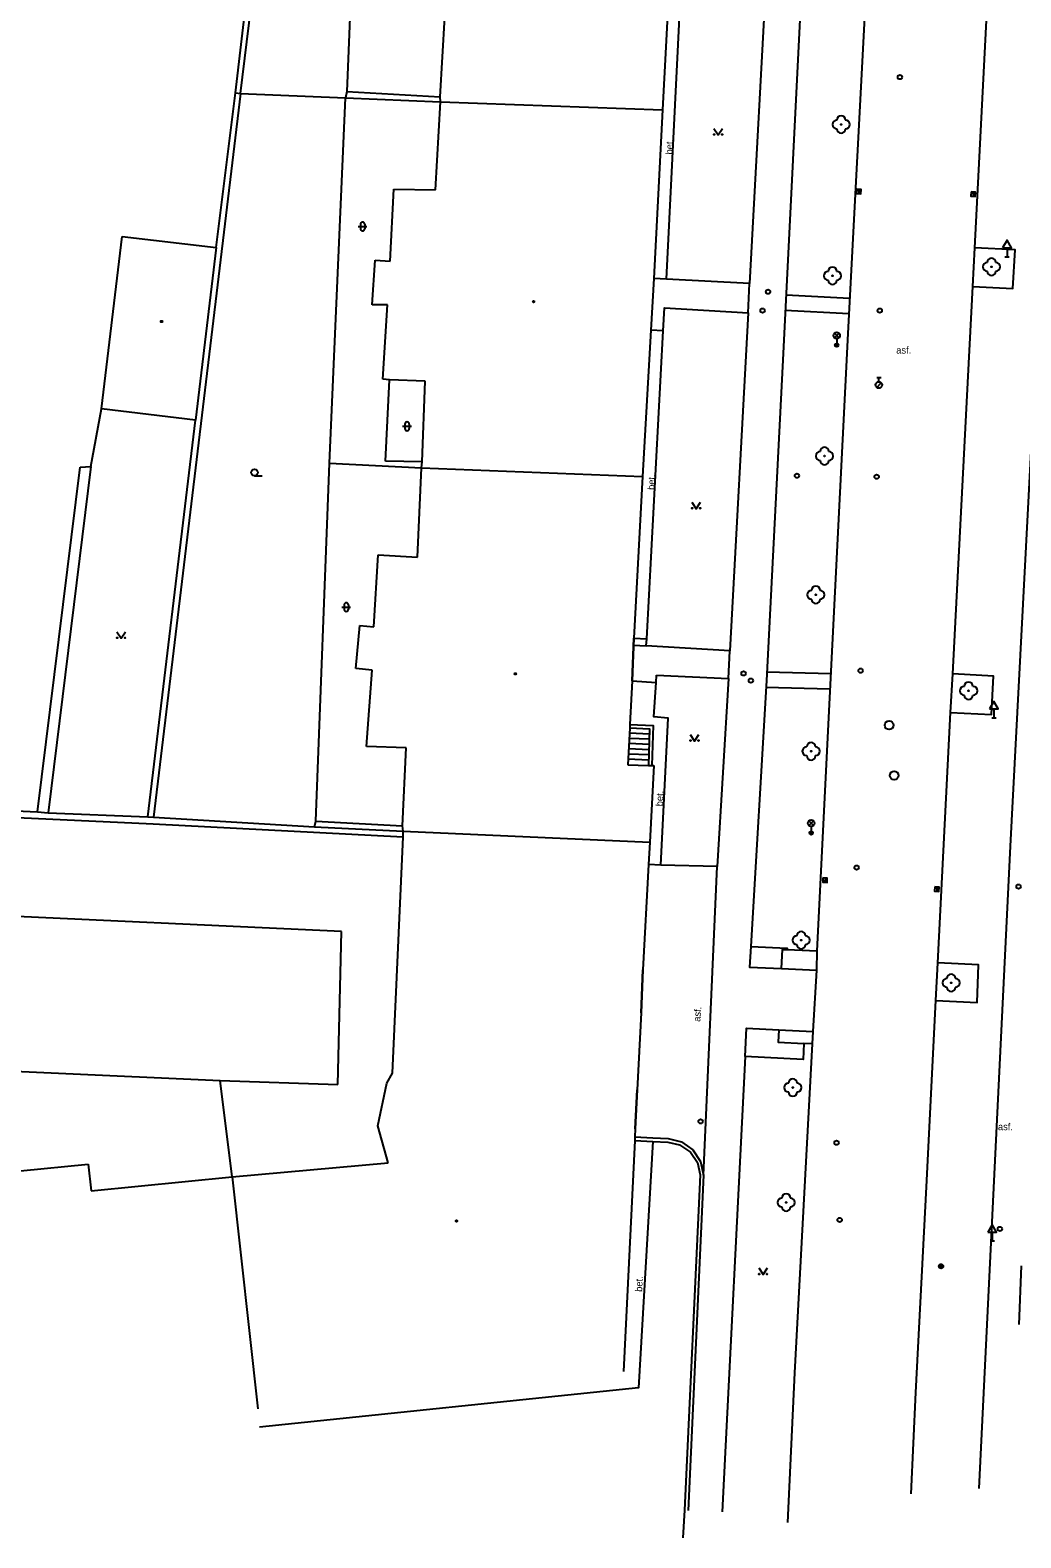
# Model space of a CAD drawing. Extents: x -599770 to -598493, y -1162076 to -1159209.
# Drawn here: x -599116.6 to -599059.8, y -1159858.3 to -1159771.9 of the extents above; entities that cross this region are included whole.
import ezdxf

# ---------------------------------------------------------------- set-up
doc = ezdxf.new("R2010")
doc.units = 0
doc.layers.add('Podklad', color=7, linetype='Continuous')

msp = doc.modelspace()

# ---------------------------------------------------------------- linework, layer by layer
at = {"layer": 'Podklad'}
for p, q in [((-599069.114, -1159781.055), (-599069.126, -1159781.305)), ((-599062.563, -1159781.215), (-599062.577, -1159781.465)), ((-599097.813, -1159783.188), (-599097.313, -1159783.188)), ((-599097.688, -1159783.063), (-599097.688, -1159783.313)), ((-599097.438, -1159783.063), (-599097.438, -1159783.313)), ((-599060.63, -1159784.411), (-599060.63, -1159784.92)), ((-599060.755, -1159784.92), (-599060.505, -1159784.92)), ((-599070.523, -1159789.56), (-599070.258, -1159789.295)), ((-599070.523, -1159789.295), (-599070.258, -1159789.56)), ((-599070.39, -1159789.615), (-599070.39, -1159789.99)), ((-599068.099, -1159792.406), (-599067.834, -1159792.141)), ((-599068.095, -1159791.832), (-599067.845, -1159791.832)), ((-599067.97, -1159792.082), (-599067.97, -1159791.832)), ((-599095.263, -1159794.638), (-599094.763, -1159794.638)), ((-599095.138, -1159794.513), (-599095.138, -1159794.763)), ((-599094.888, -1159794.513), (-599094.888, -1159794.763)), ((-599103.75, -1159797.477), (-599103.312, -1159797.477)), ((-599098.743, -1159804.998), (-599098.243, -1159804.998)), ((-599098.618, -1159804.873), (-599098.618, -1159805.123)), ((-599098.368, -1159804.873), (-599098.368, -1159805.123)), ((-599061.505, -1159811.34), (-599061.255, -1159811.34)), ((-599061.38, -1159810.831), (-599061.38, -1159811.34)), ((-599071.983, -1159817.51), (-599071.718, -1159817.245)), ((-599071.983, -1159817.245), (-599071.718, -1159817.51)), ((-599071.85, -1159817.565), (-599071.85, -1159817.94)), ((-599071.053, -1159820.515), (-599071.067, -1159820.765)), ((-599064.647, -1159821.035), (-599064.653, -1159821.285)), ((-599061.48, -1159840.811), (-599061.48, -1159841.32)), ((-599061.605, -1159841.32), (-599061.355, -1159841.32))]:
    msp.add_line(p, q, dxfattribs=at)
for points in [[(-599064.88, -1159693.54), (-599068.63, -1159693.23), (-599068.733, -1159695.648), (-599069.063, -1159703.385), (-599069.128, -1159704.902), (-599069.27, -1159708.23), (-599070.26, -1159727.69), (-599071.34, -1159749.23), (-599072.37, -1159768.64), (-599073.44, -1159790.08), (-599074.42, -1159809.21), (-599075.32, -1159824.45)], [(-599064.88, -1159693.54), (-599064.99, -1159695.953), (-599065.336, -1159703.585), (-599065.404, -1159705.083), (-599065.6, -1159709.4), (-599066.57, -1159727.92), (-599067.66, -1159748.75), (-599068.68, -1159768.99), (-599069.76, -1159789.32), (-599070.8, -1159810.19), (-599071.53, -1159824.7)], [(-599054.74, -1159709.09), (-599055.16, -1159717.05), (-599056.53, -1159743.1), (-599058.18, -1159775.24), (-599060.45, -1159818.7), (-599062.24, -1159855.51)], [(-599062.47, -1159784.41), (-599062.25, -1159779.95), (-599061.63, -1159768.01), (-599060.72, -1159751.04)], [(-599104.84, -1159775.52), (-599102.37, -1159754.5)], [(-599104.55, -1159775.56), (-599101.98, -1159754.51)], [(-599097.63, -1159754.74), (-599098.46, -1159775.46)], [(-599079.3, -1159769.29), (-599079.18, -1159766.89), (-599074.34, -1159767.07), (-599075.38, -1159786.45), (-599080.15, -1159786.21)], [(-599080, -1159769.26), (-599080.37, -1159776.51)], [(-599080.15, -1159786.21), (-599079.3, -1159769.29)], [(-599093.11, -1159775.75), (-599092.84, -1159771.18)], [(-599104.55, -1159775.56), (-599109.55, -1159817.03)], [(-599105.95, -1159784.4), (-599104.84, -1159775.52)], [(-599104.84, -1159775.52), (-599104.55, -1159775.56)], [(-599104.55, -1159775.56), (-599098.54, -1159775.82)], [(-599099.45, -1159796.75), (-599098.54, -1159775.82)], [(-599098.46, -1159775.46), (-599098.54, -1159775.82)], [(-599098.54, -1159775.82), (-599093.09, -1159776.05)], [(-599098.46, -1159775.46), (-599093.11, -1159775.75)], [(-599093.39, -1159781.08), (-599093.09, -1159776.05)], [(-599093.09, -1159776.05), (-599093.11, -1159775.75)], [(-599093.09, -1159776.05), (-599080.37, -1159776.51)], [(-599080.37, -1159776.51), (-599080.87, -1159786.17)], [(-599077.43, -1159777.565), (-599077.18, -1159777.94), (-599076.93, -1159777.565)], [(-599095.98, -1159785.18), (-599095.76, -1159781.05)], [(-599095.76, -1159781.05), (-599093.39, -1159781.08)], [(-599112.53, -1159793.63), (-599111.34, -1159783.76)], [(-599111.34, -1159783.76), (-599105.95, -1159784.4)], [(-599105.95, -1159784.4), (-599107.14, -1159794.28)], [(-599062.59, -1159786.63), (-599062.47, -1159784.41)], [(-599062.59, -1159786.63), (-599060.29, -1159786.75), (-599060.16, -1159784.53), (-599062.47, -1159784.41)], [(-599097.02, -1159787.68), (-599096.84, -1159785.11)], [(-599096.84, -1159785.11), (-599095.98, -1159785.18)], [(-599080.87, -1159786.17), (-599081.04, -1159789.13)], [(-599080.15, -1159786.21), (-599080.87, -1159786.17)], [(-599075.47, -1159788.13), (-599075.38, -1159786.45)], [(-599073.292, -1159787.112), (-599069.653, -1159787.299)], [(-599063.74, -1159808.83), (-599062.86, -1159791.77), (-599062.59, -1159786.63)], [(-599096.14, -1159787.68), (-599097.02, -1159787.68)], [(-599096.39, -1159791.93), (-599096.14, -1159787.68)], [(-599080.33, -1159789.17), (-599080.26, -1159787.84), (-599075.47, -1159788.13), (-599076.51, -1159807.51), (-599081.3, -1159807.21)], [(-599069.7, -1159788.198), (-599073.337, -1159788.011)], [(-599081.04, -1159789.13), (-599081.52, -1159797.52)], [(-599081.28, -1159806.82), (-599080.33, -1159789.17)], [(-599080.33, -1159789.17), (-599081.04, -1159789.13)], [(-599096.01, -1159791.98), (-599096.39, -1159791.93)], [(-599096.25, -1159796.64), (-599096.01, -1159791.98)], [(-599093.98, -1159792.06), (-599096.01, -1159791.98)], [(-599094.14, -1159796.68), (-599093.98, -1159792.06)], [(-599113.13, -1159796.95), (-599112.53, -1159793.63)], [(-599107.14, -1159794.28), (-599112.53, -1159793.63)], [(-599109.87, -1159817.02), (-599107.14, -1159794.28)], [(-599100.24, -1159817.26), (-599099.45, -1159796.75)], [(-599099.45, -1159796.75), (-599094.19, -1159797.01)], [(-599094.14, -1159796.68), (-599096.25, -1159796.64)], [(-599094.19, -1159797.01), (-599094.14, -1159796.68)], [(-599116.19, -1159816.73), (-599113.74, -1159796.98)], [(-599113.13, -1159796.95), (-599115.57, -1159816.78)], [(-599113.74, -1159796.98), (-599113.13, -1159796.95)], [(-599094.41, -1159802.13), (-599094.19, -1159797.01)], [(-599094.19, -1159797.01), (-599081.52, -1159797.52)], [(-599081.52, -1159797.52), (-599082.01, -1159806.77)], [(-599078.69, -1159798.985), (-599078.44, -1159799.36), (-599078.19, -1159798.985)], [(-599096.92, -1159806.13), (-599096.66, -1159802.01)], [(-599096.66, -1159802.01), (-599094.41, -1159802.13)], [(-599097.94, -1159808.51), (-599097.72, -1159806.05)], [(-599097.72, -1159806.05), (-599096.92, -1159806.13)], [(-599111.65, -1159806.405), (-599111.4, -1159806.78), (-599111.15, -1159806.405)], [(-599082.12, -1159809.22), (-599082.01, -1159806.77)], [(-599082.01, -1159806.77), (-599082.12, -1159809.22)], [(-599082.028, -1159807.18), (-599081.3, -1159807.21)], [(-599082.01, -1159806.77), (-599081.28, -1159806.82)], [(-599081.3, -1159807.21), (-599081.28, -1159806.82)], [(-599076.6, -1159809.08), (-599076.51, -1159807.51)], [(-599097.02, -1159808.62), (-599097.94, -1159808.51)], [(-599097.34, -1159812.99), (-599097.02, -1159808.62)], [(-599080.74, -1159809.32), (-599080.71, -1159808.9)], [(-599080.71, -1159808.9), (-599076.6, -1159809.08), (-599077.24, -1159819.87), (-599080.47, -1159819.78)], [(-599074.394, -1159808.701), (-599070.731, -1159808.799)], [(-599063.86, -1159811.04), (-599063.74, -1159808.83)], [(-599063.86, -1159811.04), (-599061.52, -1159811.15), (-599061.41, -1159808.95), (-599063.74, -1159808.83)], [(-599082.12, -1159809.22), (-599082.24, -1159811.72)], [(-599082.12, -1159809.22), (-599080.74, -1159809.32)], [(-599080.47, -1159819.78), (-599080.04, -1159811.36), (-599080.87, -1159811.29), (-599080.74, -1159809.32)], [(-599070.775, -1159809.698), (-599074.443, -1159809.597)], [(-599064.6, -1159825.38), (-599063.86, -1159811.04)], [(-599082.25, -1159811.92), (-599082.35, -1159814.03)], [(-599081.12, -1159812.27), (-599082.26, -1159812.22)], [(-599082.24, -1159811.72), (-599082.25, -1159811.92)], [(-599082.25, -1159811.92), (-599081.11, -1159811.97), (-599081.18, -1159814.07)], [(-599082.24, -1159811.72), (-599080.9, -1159811.78), (-599080.98, -1159814.08)], [(-599078.79, -1159812.295), (-599078.54, -1159812.67), (-599078.29, -1159812.295)], [(-599095.06, -1159813.06), (-599097.34, -1159812.99)], [(-599095.27, -1159817.53), (-599095.06, -1159813.06)], [(-599081.15, -1159813.17), (-599082.31, -1159813.12)], [(-599081.14, -1159812.87), (-599082.29, -1159812.82)], [(-599081.13, -1159812.57), (-599082.28, -1159812.52)], [(-599082.35, -1159814.03), (-599081.18, -1159814.07)], [(-599081.17, -1159813.77), (-599082.34, -1159813.72)], [(-599081.16, -1159813.47), (-599082.32, -1159813.42)], [(-599081.18, -1159814.07), (-599080.98, -1159814.08)], [(-599080.86, -1159814.08), (-599081.1, -1159818.46)], [(-599080.98, -1159814.08), (-599080.86, -1159814.08)], [(-599141.59, -1159815.93), (-599109.56, -1159817.41)], [(-599119.93, -1159816.55), (-599116.19, -1159816.73)], [(-599116.19, -1159816.73), (-599115.57, -1159816.78)], [(-599115.57, -1159816.78), (-599109.87, -1159817.02)], [(-599109.87, -1159817.02), (-599109.55, -1159817.03)], [(-599109.56, -1159817.41), (-599095.24, -1159818.17)], [(-599109.55, -1159817.03), (-599100.31, -1159817.58)], [(-599100.31, -1159817.58), (-599100.24, -1159817.26)], [(-599100.31, -1159817.58), (-599095.24, -1159817.83)], [(-599100.24, -1159817.26), (-599095.27, -1159817.53)], [(-599095.24, -1159817.83), (-599095.27, -1159817.53)], [(-599095.84, -1159831.71), (-599095.24, -1159818.17)], [(-599095.24, -1159817.83), (-599081.1, -1159818.46)], [(-599095.24, -1159818.17), (-599095.24, -1159817.83)], [(-599081.1, -1159818.46), (-599081.17, -1159819.75)], [(-599081.17, -1159819.75), (-599081.5, -1159825.78)], [(-599080.47, -1159819.78), (-599081.17, -1159819.75)], [(-599078.02, -1159837.54), (-599077.24, -1159819.87)], [(-599098.76, -1159823.58), (-599141.77, -1159821.6)], [(-599098.98, -1159832.36), (-599098.76, -1159823.58)], [(-599075.32, -1159824.45), (-599075.38, -1159825.63), (-599073.55, -1159825.71)], [(-599075.32, -1159824.45), (-599073.22, -1159824.54), (-599073.22, -1159824.62)], [(-599073.55, -1159825.71), (-599073.5, -1159824.61), (-599073.22, -1159824.62)], [(-599073.22, -1159824.62), (-599071.53, -1159824.7)], [(-599071.53, -1159824.7), (-599071.55, -1159825.8)], [(-599081.59, -1159828.25), (-599081.5, -1159825.78)], [(-599081.5, -1159825.78), (-599081.59, -1159828.25)], [(-599073.55, -1159825.71), (-599071.55, -1159825.8)], [(-599071.55, -1159825.8), (-599071.76, -1159829.31)], [(-599064.71, -1159827.54), (-599064.6, -1159825.38)], [(-599064.71, -1159827.54), (-599062.35, -1159827.66), (-599062.27, -1159825.5), (-599064.6, -1159825.38)], [(-599066.12, -1159855.81), (-599065.85, -1159850), (-599065.25, -1159838.22), (-599064.71, -1159827.54)], [(-599081.59, -1159828.25), (-599081.82, -1159832.65)], [(-599075.64, -1159830.75), (-599075.56, -1159829.13), (-599073.71, -1159829.22)], [(-599073.71, -1159829.22), (-599073.74, -1159829.92), (-599072.27, -1159830)], [(-599073.71, -1159829.22), (-599071.76, -1159829.31)], [(-599071.76, -1159829.31), (-599071.8, -1159830.02)], [(-599072.27, -1159830), (-599072.32, -1159830.92), (-599075.64, -1159830.75)], [(-599071.8, -1159830.02), (-599072.8, -1159848.88), (-599073.21, -1159857.45)], [(-599071.8, -1159830.02), (-599072.27, -1159830)], [(-599124.69, -1159831.27), (-599105.72, -1159832.12)], [(-599075.64, -1159830.75), (-599076.95, -1159856.84)], [(-599105.72, -1159832.12), (-599098.98, -1159832.36)], [(-599105.03, -1159837.65), (-599105.72, -1159832.12)], [(-599096.68, -1159834.73), (-599096.17, -1159832.27)], [(-599096.17, -1159832.27), (-599095.84, -1159831.71)], [(-599081.93, -1159834.9), (-599081.82, -1159832.65)], [(-599081.82, -1159832.65), (-599081.93, -1159834.9)], [(-599096.1, -1159836.84), (-599096.68, -1159834.73)], [(-599080.93, -1159835.61), (-599081.74, -1159849.73), (-599103.46, -1159851.99)], [(-599081.96, -1159835.56), (-599082.6, -1159848.79)], [(-599081.95, -1159835.36), (-599081.96, -1159835.56)], [(-599081.96, -1159835.56), (-599080.93, -1159835.61)], [(-599081.93, -1159834.9), (-599081.95, -1159835.36)], [(-599081.95, -1159835.36), (-599080.92, -1159835.41), (-599080.05, -1159835.45), (-599079.28, -1159835.64), (-599078.63, -1159836.1), (-599078.19, -1159836.76), (-599078.02, -1159837.54)], [(-599080.93, -1159835.61), (-599080.06, -1159835.65), (-599079.39, -1159835.81), (-599078.77, -1159836.23), (-599078.37, -1159836.83), (-599078.22, -1159837.53)], [(-599117.16, -1159837.3), (-599113.29, -1159836.92)], [(-599113.29, -1159836.92), (-599113.12, -1159838.45)], [(-599105.03, -1159837.65), (-599096.1, -1159836.84)], [(-599113.12, -1159838.45), (-599105.03, -1159837.65)], [(-599105.03, -1159837.65), (-599103.57, -1159850.93)], [(-599078.22, -1159837.53), (-599079.11, -1159856.75), (-599079.21, -1159858.33)], [(-599078.02, -1159837.54), (-599078.91, -1159856.76)], [(-599074.86, -1159842.865), (-599074.61, -1159843.24), (-599074.36, -1159842.865)], [(-599059.94, -1159846.1), (-599059.8, -1159842.75)]]:
    msp.add_lwpolyline(points, dxfattribs=at)
for points in [[(-599069.238, -1159781.049), (-599069.251, -1159781.298), (-599069.002, -1159781.311), (-599068.989, -1159781.062)], [(-599062.688, -1159781.208), (-599062.702, -1159781.458), (-599062.452, -1159781.472), (-599062.438, -1159781.222)], [(-599060.88, -1159784.411), (-599060.38, -1159784.411), (-599060.63, -1159783.978)], [(-599061.63, -1159810.831), (-599061.13, -1159810.831), (-599061.38, -1159810.398)], [(-599071.178, -1159820.509), (-599071.191, -1159820.758), (-599070.942, -1159820.771), (-599070.929, -1159820.522)], [(-599064.772, -1159821.032), (-599064.778, -1159821.281), (-599064.528, -1159821.288), (-599064.522, -1159821.038)], [(-599061.73, -1159840.811), (-599061.23, -1159840.811), (-599061.48, -1159840.378)]]:
    msp.add_lwpolyline(points, close=True, dxfattribs=at)
for centre, radius in [((-599066.77, -1159774.63), 0.125), ((-599070.13, -1159777.34), 0.025), ((-599077.405, -1159777.915), 0.025), ((-599076.955, -1159777.915), 0.025), ((-599061.52, -1159785.5), 0.025), ((-599070.63, -1159786.01), 0.025), ((-599074.32, -1159786.93), 0.125), ((-599087.76, -1159787.5), 0.045), ((-599087.76, -1159787.5), 0.0199), ((-599074.64, -1159788.01), 0.125), ((-599067.92, -1159788.01), 0.125), ((-599109.08, -1159788.63), 0.045), ((-599109.08, -1159788.63), 0.0199), ((-599070.39, -1159789.427), 0.188), ((-599070.39, -1159789.99), 0.1), ((-599070.39, -1159789.99), 0.0723), ((-599070.39, -1159789.99), 0.0438), ((-599067.97, -1159792.27), 0.188), ((-599071.09, -1159796.34), 0.025), ((-599103.75, -1159797.29), 0.188), ((-599072.67, -1159797.47), 0.125), ((-599068.1, -1159797.53), 0.125), ((-599078.665, -1159799.335), 0.025), ((-599078.215, -1159799.335), 0.025), ((-599071.59, -1159804.29), 0.025), ((-599111.625, -1159806.755), 0.025), ((-599111.175, -1159806.755), 0.025), ((-599088.8, -1159808.82), 0.045), ((-599088.8, -1159808.82), 0.0199), ((-599075.73, -1159808.8), 0.125), ((-599069.02, -1159808.64), 0.125), ((-599075.31, -1159809.21), 0.125), ((-599062.83, -1159809.79), 0.025), ((-599067.39, -1159811.77), 0.25), ((-599078.765, -1159812.645), 0.025), ((-599078.315, -1159812.645), 0.025), ((-599071.86, -1159813.26), 0.025), ((-599067.1, -1159814.64), 0.25), ((-599071.85, -1159817.378), 0.188), ((-599071.85, -1159817.94), 0.1), ((-599071.85, -1159817.94), 0.0723), ((-599071.85, -1159817.94), 0.0438), ((-599069.25, -1159819.92), 0.125), ((-599059.97, -1159821.01), 0.125), ((-599072.43, -1159824.08), 0.025), ((-599063.83, -1159826.53), 0.025), ((-599072.91, -1159832.53), 0.025), ((-599078.19, -1159834.47), 0.125), ((-599070.4, -1159835.69), 0.125), ((-599073.29, -1159839.11), 0.025), ((-599070.22, -1159840.11), 0.125), ((-599092.18, -1159840.18), 0.045), ((-599092.18, -1159840.18), 0.0199), ((-599061.04, -1159840.63), 0.125), ((-599074.835, -1159843.215), 0.025), ((-599074.385, -1159843.215), 0.025), ((-599064.41, -1159842.77), 0.125), ((-599064.41, -1159842.77), 0.1), ((-599064.41, -1159842.77), 0.075), ((-599064.41, -1159842.77), 0.05), ((-599064.41, -1159842.77), 0.025)]:
    msp.add_circle(centre, radius, dxfattribs=at)
for centre, radius, start, end in [((-599070.13, -1159777.09), 0.25, 0, 180), ((-599070.38, -1159777.34), 0.25, 90, 270), ((-599070.13, -1159777.59), 0.25, 180, 0), ((-599069.88, -1159777.34), 0.25, 270, 90), ((-599097.563, -1159783.063), 0.125, 0, 180), ((-599097.563, -1159783.313), 0.125, 180, 0), ((-599070.63, -1159785.76), 0.25, 0, 180), ((-599061.77, -1159785.5), 0.25, 90, 270), ((-599061.52, -1159785.25), 0.25, 0, 180), ((-599061.27, -1159785.5), 0.25, 270, 90), ((-599070.88, -1159786.01), 0.25, 90, 270), ((-599070.63, -1159786.26), 0.25, 180, 0), ((-599070.38, -1159786.01), 0.25, 270, 90), ((-599061.52, -1159785.75), 0.25, 180, 0), ((-599095.013, -1159794.513), 0.125, 0, 180), ((-599095.013, -1159794.763), 0.125, 180, 0), ((-599071.09, -1159796.09), 0.25, 0, 180), ((-599071.34, -1159796.34), 0.25, 90, 270), ((-599071.09, -1159796.59), 0.25, 180, 0), ((-599070.84, -1159796.34), 0.25, 270, 90), ((-599071.84, -1159804.29), 0.25, 90, 270), ((-599071.59, -1159804.04), 0.25, 0, 180), ((-599071.59, -1159804.54), 0.25, 180, 0), ((-599071.34, -1159804.29), 0.25, 270, 90), ((-599098.493, -1159804.873), 0.125, 0, 180), ((-599098.493, -1159805.123), 0.125, 180, 0), ((-599063.08, -1159809.79), 0.25, 90, 270), ((-599062.83, -1159809.54), 0.25, 0, 180), ((-599062.58, -1159809.79), 0.25, 270, 90), ((-599062.83, -1159810.04), 0.25, 180, 0), ((-599072.11, -1159813.26), 0.25, 90, 270), ((-599071.86, -1159813.01), 0.25, 0, 180), ((-599071.61, -1159813.26), 0.25, 270, 90), ((-599071.86, -1159813.51), 0.25, 180, 0), ((-599072.43, -1159823.83), 0.25, 0, 180), ((-599072.68, -1159824.08), 0.25, 90, 270), ((-599072.43, -1159824.33), 0.25, 180, 0), ((-599072.18, -1159824.08), 0.25, 270, 90), ((-599063.83, -1159826.28), 0.25, 0, 180), ((-599064.08, -1159826.53), 0.25, 90, 270), ((-599063.83, -1159826.78), 0.25, 180, 0), ((-599063.58, -1159826.53), 0.25, 270, 90), ((-599072.91, -1159832.28), 0.25, 0, 180), ((-599073.16, -1159832.53), 0.25, 90, 270), ((-599072.91, -1159832.78), 0.25, 180, 0), ((-599072.66, -1159832.53), 0.25, 270, 90), ((-599073.54, -1159839.11), 0.25, 90, 270), ((-599073.29, -1159838.86), 0.25, 0, 180), ((-599073.04, -1159839.11), 0.25, 270, 90), ((-599073.29, -1159839.36), 0.25, 180, 0)]:
    msp.add_arc(centre, radius, start, end, dxfattribs=at)

# ---------------------------------------------------------------- texts
for s, rotation, p in [('bet.', 87.21, (-599079.8, -1159779.07)), ('bet.', 87.21, (-599080.83, -1159798.29)), ('bet.', 87.21, (-599080.36, -1159816.42)), ('asf.', 85.45, (-599078.21, -1159828.77)), ('bet.', 87.21, (-599081.54, -1159844.24))]:
    msp.add_text(s, height=0.4, rotation=rotation, dxfattribs=at).set_placement(p)
for p in [(-599066.98, -1159790.47), (-599061.15, -1159834.97)]:
    msp.add_text('asf.', height=0.4, dxfattribs=at).set_placement(p)

doc.saveas('drawing.dxf')
